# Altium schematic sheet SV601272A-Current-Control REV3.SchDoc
size 431 x 279 mm; Date: Not shown in title block; ApprovedBy: Not shown in title block; CheckedBy: Not shown in title block; Author: Not shown in title block; CompanyName: Not shown in title block; Engineer: Not shown in title block; Organization: Not shown in title block; Address1: Not shown in title block; Address2: Not shown in title block; Address3: Not shown in title block; Address4: Not shown in title block; DocumentNumber: 6; Revision: Use project parameter SCH_Rev; SheetNumber: 6; SheetTotal: 11; PageSetup: Record=PageOptions¦CenterHorizontal=True¦CenterVertical=True¦PrintScale=1.00¦XCorrection=1.00¦YCorrection=1.00¦PrintKind=0¦BorderSize=5000000¦LeftOffset=0¦BottomOffset=0¦Orientation=2¦PaperLength=1000¦PaperWidth=1000¦Scale=100¦PaperSource=15¦PrintQuality=600¦MediaType=1¦DitherType=10¦PaperKind=Letter¦PrintScaleMode=1
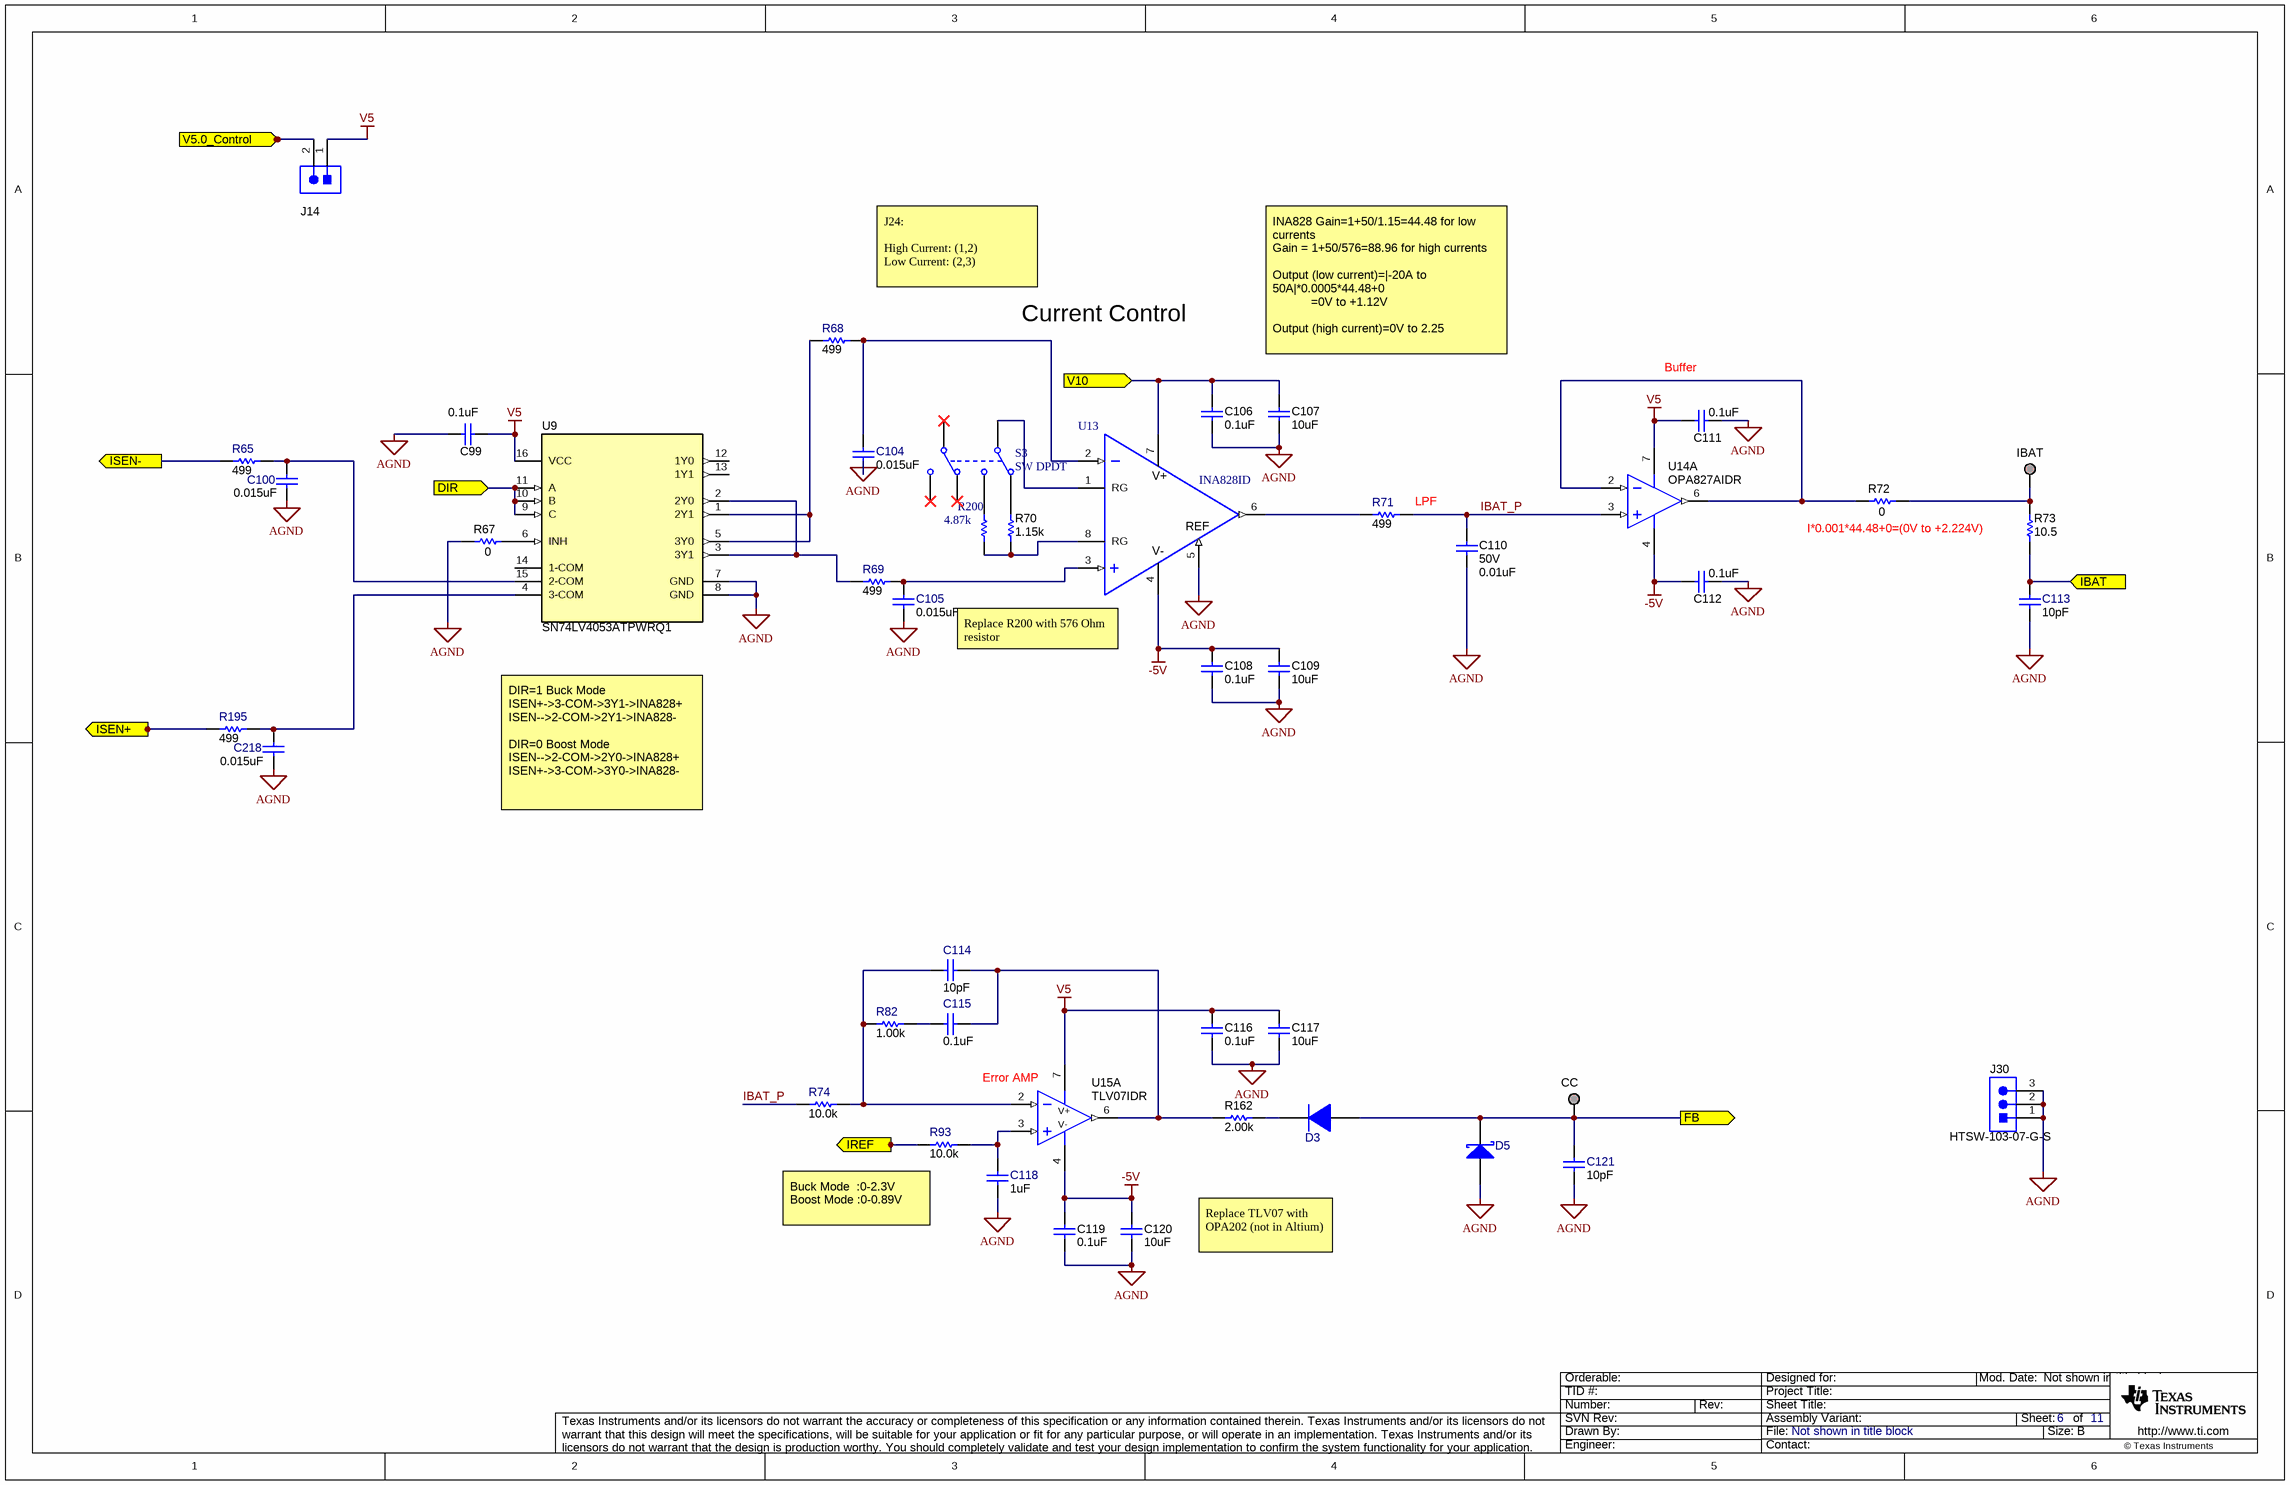
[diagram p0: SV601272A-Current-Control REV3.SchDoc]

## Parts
C99  ValueDisplayed: 0.1uF  [0603]  (hidden comment: Capacitor)
C100  ValueDisplayed: 0.015uF  [0603]  (hidden comment: Capacitor)
C104  ValueDisplayed: 0.015uF  [0603]  (hidden comment: Capacitor)
C105  ValueDisplayed: 0.015uF  [0603]  (hidden comment: Capacitor)
C106  ValueDisplayed: 0.1uF  [0603]  (hidden comment: Capacitor)
C107  ValueDisplayed: 10uF  [0805_HV]  (hidden comment: Capacitor)
C108  ValueDisplayed: 0.1uF  [0603]  (hidden comment: Capacitor)
C109  ValueDisplayed: 10uF  [0805_HV]  (hidden comment: Capacitor)
C110  VDC_V: 50V  ValueDisplayed: 0.01uF  [0603]  (hidden comment: GCM188R71H103KA37D)
C111  ValueDisplayed: 0.1uF  [0603]  (hidden comment: Capacitor)
C112  ValueDisplayed: 0.1uF  [0603]  (hidden comment: Capacitor)
C113  ValueDisplayed: 10pF  [0603]  (hidden comment: Capacitor)
C114  ValueDisplayed: 10pF  [0603]  (hidden comment: Capacitor)
C115  ValueDisplayed: 0.1uF  [0603]  (hidden comment: Capacitor)
C116  ValueDisplayed: 0.1uF  [0603]  (hidden comment: Capacitor)
C117  ValueDisplayed: 10uF  [0805_HV]  (hidden comment: Capacitor)
C118  ValueDisplayed: 1uF  [0603]  (hidden comment: Capacitor)
C119  ValueDisplayed: 0.1uF  [0603]  (hidden comment: Capacitor)
C120  ValueDisplayed: 10uF  [0805_HV]  (hidden comment: Capacitor)
C121  ValueDisplayed: 10pF  [0603]  (hidden comment: Capacitor)
C218  ValueDisplayed: 0.015uF  [0603]  (hidden comment: Capacitor)
CC  Pogo Pad  [PogoPad]  (value not drawn)  (no BOM)
D3  DIODE  [SOD-523]  (value not drawn)
D5  DIODE_SCHOTTKY  [SOD-323]  (value not drawn)
IBAT  Pogo Pad  [PogoPad]  (value not drawn)  (no BOM)
J14  HTSW-102-07-G-S  [Samtec_HTSW-102-07-G-S]  (value not drawn)
J30  HTSW-103-07-G-S  [Samtec_HTSW-103-07-G-S]
R65  ValueDisplayed: 499  [0603]  (hidden comment: Resistor)
R67  ValueDisplayed: 0  [0603]  (hidden comment: Resistor)
R68  ValueDisplayed: 499  [0603]  (hidden comment: Resistor)
R69  ValueDisplayed: 499  [0603]  (hidden comment: Resistor)
R70  1.15k  [0603]
R71  ValueDisplayed: 499  [0603]  (hidden comment: Resistor)
R72  ValueDisplayed: 0  [0603]  (hidden comment: Resistor)
R73  ValueDisplayed: 10.5  [0603]  (hidden comment: RC0603FR-0710R5L)
R74  ValueDisplayed: 10.0k  [0603]  (hidden comment: Resistor)
R82  ValueDisplayed: 1.00k  [0603]  (hidden comment: Resistor)
R93  ValueDisplayed: 10.0k  [0603]  (hidden comment: Resistor)
R162  ValueDisplayed: 2.00k  [0603]  (hidden comment: RT0603DRE072KL)
R195  ValueDisplayed: 499  [0603]  (hidden comment: Resistor)
R200  ValueDisplayed: 4.87k  [0603]  (hidden comment: RG1608P-4871-B-T5)
S3  SW DPDT  [SOT23-6_N]
U9  SN74LV4053ATPWRQ1  [PW0016A_L]
U13  INA828ID  [D0008A_N]
U14  OPA827AIDR  [D0008A_L]  (part A of 2)
U15  TLV07IDR  [D0008A_N]  (part A of 2)

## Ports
DIR, FB, IBAT, IREF, ISEN+, ISEN-, V5.0_Control, V10

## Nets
-5V: C108.1 C109.1 C112.1 C119.1 C120.1 U13.4(V-) U14.4(V-) U15.4(V-)
AGND: C99.1 C100.2 C104.2 C105.2 C106.2 C107.2 C108.2 C109.2 C110.2 C111.2 C112.2 C113.1 C116.2 C117.2 C118.1 C119.2 C120.2 C121.1 C218.2 D5.2(A) J30.1 J30.2 J30.3 R67.1 U9.7(GND) U9.8(GND) U13.5(REF)
V5: C99.2 C111.1 C116.1 C117.1 J14.1 U9.16(VCC) U14.7(V+) U15.7(V+)
DIR: U9.9(C) U9.10(B) U9.11(A) ; port DIR
FB: C121.2 CC.1 D3.2(A) D5.1(K) ; port FB
IBAT: C113.2 R73.1 ; port IBAT
IBAT_P: C110.1 R71.1 R74.1 U14.3(IN+)
IREF: R93.1 ; port IREF
ISEN+: R195.2 ; port ISEN+
ISEN-: R65.2 ; port ISEN-
V5.0_Control: J14.2 ; port V5.0_Control
V10: C106.1 C107.1 U13.7(V+) ; port V10
NetC100_1: C100.1 R65.1 U9.15(2-COM)
NetC104_1: C104.1 R68.1 U13.2(IN-)
NetC105_1: C105.1 R69.1 U13.3(IN+)
NetC114_1: C114.1 R74.2 R82.1 U15.2(IN-)
NetC114_2: C114.2 C115.1 R162.1 U15.6(OUT)
NetC115_2: C115.2 R82.2
NetC118_2: C118.2 R93.2 U15.3(IN+)
NetC218_1: C218.1 R195.1 U9.4(3-COM)
NetD3_1: D3.1(K) R162.2
NetIBAT_1: IBAT.1 R72.2 R73.2
NetR67_2: R67.2 U9.6(INH)
NetR68_2: R68.2 U9.1(2Y1) U9.5(3Y0)
NetR69_2: R69.2 U9.2(2Y0) U9.3(3Y1)
NetR70_1: R70.1 R200.1 U13.8(RG)
NetR70_2: R70.2 S3.2(NC1)
NetR71_2: R71.2 U13.6(OUT)
NetR72_1: R72.1 U14.2(IN-) U14.6(OUT)
NetR200_2: R200.2 S3.3(NO1)
NetS3_1: S3.1(COMMON1) U13.1(RG)

Not connected (* = marked no-connect by the designer): S3 4(NC2)* 5(COMMON2)* 6(NO2)*; U9 12(1Y0) 13(1Y1) 14(1-COM)

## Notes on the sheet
- J24:
  High Current: (1,2)
  Low Current: (2,3)
- Current Control
- INA828 Gain=1+50/1.15=44.48 for low currents
  Gain = 1+50/576=88.96 for high currents
  Output (low current)=|-20A to 50A|*0.0005*44.48+0
  =0V to +1.12V
  Output (high current)=0V to 2.25
- (near C111) Buffer
- (near R71) LPF
- (near R72) I*0.001*44.48+0=(0V to +2.224V)
- Replace R200 with 576 Ohm resistor
- DIR=1 Buck Mode
  ISEN+->3-COM->3Y1->INA828+
  ISEN-->2-COM->2Y1->INA828-
  DIR=0 Boost Mode
  ISEN-->2-COM->2Y0->INA828+
  ISEN+->3-COM->3Y0->INA828-
- (near U15) Error AMP
- (near R93) Buck Mode  :0-2.3V
  Boost Mode :0-0.89V
- Replace TLV07 with OPA202 (not in Altium)

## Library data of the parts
C99 C106 C108 C111 C112 C116 C119 = CMP-0006752-5: CAP, CERM, 0.1 uF, 25 V, +/- 5%, X7R, 0603; PartNumber: 06033C104JAT2A; Manufacturer: AVX; Polarized: N; Value: 0.1uF; U/M: EA; Cap_F: 100nF; ESR_ohm: 0.05; Value1: 0.05 ohm; VDC_V: 25V; TaMin_C: -55°C; TaMax_C: 125°C; AEC Category: Q200; SizeArea_mm2: 1.28; SizeAreaWB_mm2: 4.68; SizeX_mm: 1.6; SizeY_mm: 0.8; SizeZ_mm: 1
C100 C104 C105 C218 = CMP-0007383-5: CAP, CERM, 0.015 uF, 16 V, +/- 10%, X7R, 0603; PartNumber: GRM188R71C153KA01D; Manufacturer: MuRata; Polarized: N; U/M: EA; Cap_F: 15nF; Value1: Unknown; VDC_V: 16V; TaMin_C: -55°C; TaMax_C: 125°C; SizeArea_mm2: 1.28; SizeAreaWB_mm2: 4.68; SizeX_mm: 1.6; SizeY_mm: 0.8; SizeZ_mm: 1; AEC Category: Q200
C107 C109 C117 C120 = CMP-0008315-2: CAP, CERM, 10 uF, 10 V, +/- 10%, X7R, 0805; PartNumber: GRM21BR71A106KE51L; Manufacturer: MuRata; Polarized: N; Value: 10uF; U/M: EA; Cap_F: 10µF; ESR_ohm: 3m; Value1: 0.003 ohm; VDC_V: 10V; TaMin_C: -55°C; TaMax_C: 125°C; Cap_Case: 0805; AEC Category: Q200; SizeArea_mm2: 2.5; SizeAreaWB_mm2: 6.75; SizeX_mm: 2; SizeY_mm: 1.25; SizeZ_mm: 1.45
C110 = CMP-0007143-4: CAP, CERM, 0.01 uF, 50 V, +/- 10%, X7R, AEC-Q200 Grade 1, 0603; Manufacturer: MuRata; TaMin_C: -55°C; Polarized: N; SizeAreaWB_mm2: 4.68; Value1: Unknown; U/M: EA; Value: 0.01uF; TaMax_C: 125°C; SizeZ_mm: 1; SizeX_mm: 1.6; SizeY_mm: 0.8; SizeArea_mm2: 1.28; CompType: Capacitor; AEC Qualified: Y; Cap_F: 10nF; AEC Category: Q200
C113 C114 C121 = CMP-0007170-4: CAP, CERM, 10 pF, 50 V, +/- 5%, C0G/NP0, 0603; PartNumber: GRM1885C1H100JA01D; Manufacturer: MuRata; Polarized: N; Value: 10pF; U/M: EA; Value1: Unknown; VDC_V: 50V; TaMin_C: -55°C; TaMax_C: 125°C; SizeArea_mm2: 1.28; SizeAreaWB_mm2: 4.68; SizeX_mm: 1.6; SizeY_mm: 0.8; SizeZ_mm: 1; AEC Category: Q200
C115 = CMP-0007334-5: CAP, CERM, 0.1 uF, 16 V, +/- 10%, X5R, 0603; PartNumber: GRM188R61C104KA01D; Manufacturer: MuRata; Polarized: N; Value: 0.1uF; U/M: EA; Cap_F: 100nF; Value1: Unknown; VDC_V: 16V; TaMin_C: -55°C; TaMax_C: 85°C; SizeArea_mm2: 1.28; SizeAreaWB_mm2: 4.68; SizeX_mm: 1.6; SizeY_mm: 0.8; SizeZ_mm: 1; AEC Category: Q200
C118 = CMP-0007302-5: CAP, CERM, 1 uF, 6.3 V, +/- 10%, X5R, 0603; PartNumber: GRM188R60J105KA01D; Manufacturer: MuRata; Polarized: N; Value: 1uF; U/M: EA; Cap_F: 1µF; Value1: Unknown; VDC_V: 6.3V; TaMin_C: -55°C; TaMax_C: 85°C; SizeArea_mm2: 1.28; SizeAreaWB_mm2: 4.68; SizeX_mm: 1.6; SizeY_mm: 0.8; SizeZ_mm: 1; AEC Category: Q200
CC IBAT = PogoPad: Pad for Pogo Pin Connector; SymbolCreator: codlsc
D3 = CMP-0076957-2: Diode, Switching, 75 V, 0.3 A, SOD-523; PartNumber: 1N4148X-TP; Manufacturer: Micro Commercial Components; U/M: EA; Vf_V: 1.25V; Value: 75V; Value1: 0.3A; Io_A: 3dA; TJmax_C: 150°C; SizeAreaWB_mm2: 5.13; SizeArea_mm2: 1.53; SizeX_mm: 1.7; SizeY_mm: 0.9; SizeZ_mm: 0.65; AEC Category: Q101; Green_Lifecycle: Not Set; Green_REACh: Incomplete
D5 = CMP-0028458-1: Diode, Schottky, 30 V, 0.2 A, SOD-323; PartNumber: BAT54WS-7-F; Manufacturer: Diodes Inc.; U/M: EA; Vf_V: 7dV; Value: 30V; Value1: 0.2A; Value2: 0.7V; Io_A: 2dA; TJmax_C: 125°C; SizeAreaWB_mm2: 8.695; SizeArea_mm2: 3.645; SizeX_mm: 2.7; SizeY_mm: 1.35; SizeZ_mm: 1; AEC Category: Q101; Green_Lifecycle: Active; Green_REACh: Passed
J14 = HTSW-102-07-G-S: Header, 100mil, 2x1, Gold, TH; Manufacturer: Samtec; SymbolCreator: a0412235; U/M: EA
J30 = HTSW-103-07-G-S: Header, 100mil, 3x1, Gold, TH; Manufacturer: Samtec; SymbolCreator: a0799628; U/M: EA
R65 R68 R69 R71 R195 = CMP-0022446-5: RES, 499, 1%, 0.1 W, AEC-Q200 Grade 0, 0603; PartNumber: CRCW0603499RFKEA; Manufacturer: Vishay-Dale; Value: 499; Value_Code: 499R; Power_W: 100mW; Value2: 0.1W; VDC_V: 75V; TempCo: 100 ppm/C; SizeArea_mm2: 1.28; SizeX_mm: 1.6; SizeY_mm: 0.8; SizeZ_mm: 1; EIA_Code: E96; AEC Category: Q200; AEC Qualified: Y; AEC Grade: 0
R67 R72 = CMP-0025874-3: RES, 0, 5%, 0.1 W, 0603; PartNumber: ERJ-3GEY0R00V; Manufacturer: Panasonic; Value: 0; Value_Code: 0000; Power_W: 100mW; Value2: 0.1W; VDC_V: 50V; TempCo: 600 ppm/C; EIA_Code: E24; U/M: EA; AEC Category: Q200; SizeArea_mm2: 1.28; SizeX_mm: 1.6; SizeY_mm: 0.8; SizeZ_mm: 1
R70 = CMP-0023872-3: RES, 1.15 k, 0.1%, 0.1 W, 0603; Manufacturer: Yageo America; PartNumber: RT0603BRD071K15L; Power_W: 100mW; TempCo: 25 ppm/C; Value_Code: 1k15; U/M: EA; EIA_Code: E192; SizeX_mm: 1.6; SizeY_mm: 0.8; SizeZ_mm: 1; SizeArea_mm2: 1.28; CompType: Resistor; Value2: 0.1W; VDC_V: 75V; AEC Category: Q200
R73 = CMP-0022749-2: RES, 10.5, 1%, 0.1 W, 0603; Manufacturer: Yageo America; Power_W: 100mW; TempCo: 200 ppm/C; Value_Code: 10R5; U/M: EA; Value: 10.5; EIA_Code: E96; SizeX_mm: 1.6; SizeY_mm: 0.8; SizeZ_mm: 1; Value2: 0.1W; SizeArea_mm2: 1.28; CompType: Resistor; VDC_V: 150V; AEC Category: Q200
R74 R93 = CMP-0022746-3: RES, 10.0 k, 1%, 0.1 W, 0603; PartNumber: RC0603FR-0710KL; Manufacturer: Yageo America; Value: 10.0k; Res_ohm: 10k; Value_Code: 10k0; Power_W: 100mW; Value2: 0.1W; VDC_V: 150V; TempCo: 200 ppm/C; SizeArea_mm2: 1.28; SizeX_mm: 1.6; SizeY_mm: 0.8; SizeZ_mm: 1; EIA_Code: E96; U/M: EA; AEC Category: Q200
R82 = CMP-0022895-3: RES, 1.00 k, 1%, 0.1 W, 0603; PartNumber: RC0603FR-071KL; Manufacturer: Yageo America; Value: 1.00k; Res_ohm: 1k; Value_Code: 1k00; Power_W: 100mW; Value2: 0.1W; VDC_V: 150V; TempCo: 200 ppm/C; SizeArea_mm2: 1.28; SizeX_mm: 1.6; SizeY_mm: 0.8; SizeZ_mm: 1; EIA_Code: E96; U/M: EA; AEC Category: Q200
R162 = CMP-0025080-3: RES, 2.00 k, 0.5%, 0.1 W, 0603; Manufacturer: Yageo America; Power_W: 100mW; TempCo: 50 ppm/C; Value_Code: 2k00; U/M: EA; Value: 2.00k; EIA_Code: E192; Res_ohm: 2k; SizeX_mm: 1.6; SizeY_mm: 0.8; SizeZ_mm: 1; Value2: 0.1W; SizeArea_mm2: 1.28; CompType: Resistor; VDC_V: 75V; AEC Category: Q200
R200 = CMP-0023560-3: RES, 4.87 k, 0.1%, 0.1 W, 0603; Manufacturer: Susumu Co Ltd; Power_W: 100mW; TempCo: 25 ppm/C; Value_Code: 4k87; U/M: EA; Value: 4.87k; EIA_Code: E192; SizeX_mm: 1.6; SizeY_mm: 0.8; SizeZ_mm: 1; Value2: 0.1W; SizeArea_mm2: 1.28; VDC_V: 75V; AEC Category: Q200
S3 = SW DPDT: Switch
U9 = CMP-0076549-1: TRIPLE 2-CHANNEL ANALOG MULTIPLEXER/DEMULTIPLEXER, PW0016A (TSSOP-16); Manufacturer: Texas Instruments; SizeAreaWB_mm2: 58.8; SizeArea_mm2: 32.0; SizeZ_mm: 1.2; SizeY_mm: 5.0; U/M: EA; CompType: IC; SizeX_mm: 6.4
U13 = CMP-0079943-1: 50-uV Offset, 7-nV/√Hz Noise, Low-Power, Precision Instrumentation Amplifier, D0008A (SOIC-8); Alternate PartNumber: INA828IDR; Alternate Manufacturer: Texas Instruments; SizeAreaWB_mm2: 56.58; SizeZ_mm: 1.75; SizeX_mm: 4.9; SizeY_mm: 6.2; SizeArea_mm2: 30.38; CompType: IC; AEC Qualified: N; AEC Category: Q200
U14 = CMP-0041267-2: Low-Noise, High-Precision, JFET-Input Operational Amplifier, 8 to 36 V, -40 to 125 degC, 8-pin SOIC (D8), Green (RoHS & no Sb/Br); Manufacturer: Texas Instruments; Vmax(V): 36; GBW(Typ)(MHz): 22; Vmin(V): 8; Iq per channel(Max)(mA): 5.2; SubFamily: Audio Operational Amplifier; Number of Channels: 1; Vn at Flatband(Typ)(nV/rtHz): 4
U15 = CMP-0079847-1: 36-V Precision, Rail-to-Rail Output, Operational Amplifier, D0008A (SOIC-8); Alternate Manufacturer: Texas Instruments; SizeAreaWB_mm2: 56.58; SizeZ_mm: 1.75; SizeX_mm: 4.9; SizeY_mm: 6.2; SizeArea_mm2: 30.38; CompType: IC; AEC Qualified: N; AEC Category: Q200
